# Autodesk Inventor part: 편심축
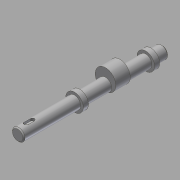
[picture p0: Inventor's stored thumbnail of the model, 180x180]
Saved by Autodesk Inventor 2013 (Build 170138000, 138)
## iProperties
Created: 2016-02
Part Number: 편심축
Material: 강철, 연강
Document SubType Name: Modeling
Designer: mduedu
Density: 1 g/cm^3
Author: mduedu
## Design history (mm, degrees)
sketch "스케치1"
  geometry: C1 r 6 at (0, 0); 1 further point
  constraints: 1 centre point, 1 coincident
  dimensions: "d0" = 12 diameter of C1
extrude "돌출1" new body sketch "스케치1" distance "d1" = 140; taper "d2" = 0 deg
chamfer "모따기1" distance "d3" = 1; stored, may be unused: second distance "d4" = 2, angle "d5" = 45 deg
node "작업 평면1"
sketch "스케치2"
  geometry: C1 r 10 at (0, 4); C2 r 6 at (0, 0) reference; 1 further point
  constraints: 1 centre point, 1 tangent, 1 vertical alignment
  dimensions: "d7" = 20 diameter of C1
extrude "돌출2" join sketch "스케치2" stored distance "d8" = 14; taper "d9" = 0 deg
node "작업 평면2"
sketch "스케치3"
  geometry: C1 r 8.5 at (0, 0); 1 further point
  constraints: 1 centre point, 1 coincident
  dimensions: "d12" = 17 diameter of C1
extrude "돌출3" join sketch "스케치3" distance "d13" = 5; taper "d14" = 0 deg
node "작업 평면3"
sketch "스케치4"
  geometry: L1 (-5, 140)-(5, 140) reference; L2 (0, 140)-(0, 0); L3 (-2, 132)-(-2, 126); L4 (2, 126)-(2, 132); A1 r 2 centre (0, 132) between (2, 132) and (-2, 132); A2 r 2 centre (0, 126) between (-2, 126) and (2, 126)
  constraints: 6 end point, 4 point on circle, 4 tangent, 2 centre point, 2 point on line, 1 midpoint, 1 parallel, 1 perpendicular
  dimensions: "d15" = 4 distance between parallel lines of L3 L4; "d17" = 6 distance edge to line of A1 L1; "d18" = 10 dimension on A2 A1
extrude "돌출4" cut sketch "스케치4" distance "d19" = 2.5; taper "d20" = 0 deg
sketch "스케치5"
  geometry: L1 (6, 55)-(6, 139) reference; L2 (-6, 55)-(-6, 139) reference; L3 (6, 115)-(-6, 115); L4 (-5, 140)-(5, 140) reference; L5 (6, 116.5)-(4.5, 115); L6 (6, 116.5)-(6, 115); L7 (4.5, 115)-(6, 115); 1 further point
  constraints: 8 end point, 4 point on line, 2 collinear, 1 perpendicular
  dimensions: "d21" = 25 distance between parallel lines of L3 L4; "d22" = 3 diameter of L5.start L3; "d24" = 45 deg angle of L3 L5
revolve "회전1" sketch "스케치5" stored, may be unused: angle "d25" = 90 deg
sketch "스케치6"
  geometry: L1 (6, 116.5)-(4.5, 115) reference; L2 (6, 113.5)-(4.5, 115) reference; 2 further points
  constraints: 1 coincident
node "작업 평면4"
sketch "스케치7"
  geometry: C1 r 8.5 at (0, -4); 1 further point
  constraints: 1 centre point, 1 coincident
  dimensions: "d27" = 17 diameter of C1
extrude "돌출5" join sketch "스케치7" distance "d29" = 5; taper "d30" = 0 deg
node "솔리드1"
other parameters: "d6" = -48, "d11" = -11
